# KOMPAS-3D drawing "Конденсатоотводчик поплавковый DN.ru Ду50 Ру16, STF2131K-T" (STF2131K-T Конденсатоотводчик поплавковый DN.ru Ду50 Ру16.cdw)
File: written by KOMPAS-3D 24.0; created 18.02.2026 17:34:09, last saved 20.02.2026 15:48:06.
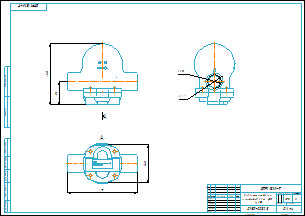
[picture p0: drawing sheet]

Document properties: art: D150-00323; Автор: R2D2; Форматы листов документа: A2; Полное имя файла: STF2131K-T Конденсатоотводчик поплавковый DN.ru Ду50 Ру16.m3d; Масса: 15.5; Наименование: Конденсатоотводчик поплавковый DN.ru Ду50 Ру16; Количество листов документа: 1; Примечание: D150-00323

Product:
- Part/product: Конденсатоотводчик поплавковый DN.ru Ду50 Ру16  | designation STF2131K-T
    Масса: 15.5
    Раздел спецификации: Прочие изделия
    Примечание: D150-00323
    additional columns: D150-00323

Views: Вид по стрелке А
Referenced files in E:\Работа\Зайцев\Для компаса\: чертеж DN.ru А3.cdt
Referenced files in E:\Работа\Зайцев\STF2131K-T Конденсатоотводчик поплавковый DN.ru Ду15-50 Ру16\DN50\: STF2131K-T Конденсатоотводчик поплавковый DN.ru Ду50 Ру16.m3d
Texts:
  чертеж DN.ru А3.cdt
  Конденсатоотводчик
  поплавковый DN.ru Ду50
  Ру16
  STF2131K-T
  prop
  Конденсатоотводчик поплавковый DN.ru Ду50 Ру16
  STF2131K-T Конденсатоотводчик поплавковый DN.ru Ду50 Ру16
Dimensions and other numbers on the sheet: 1:2; 0; 1; 2; 15,5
